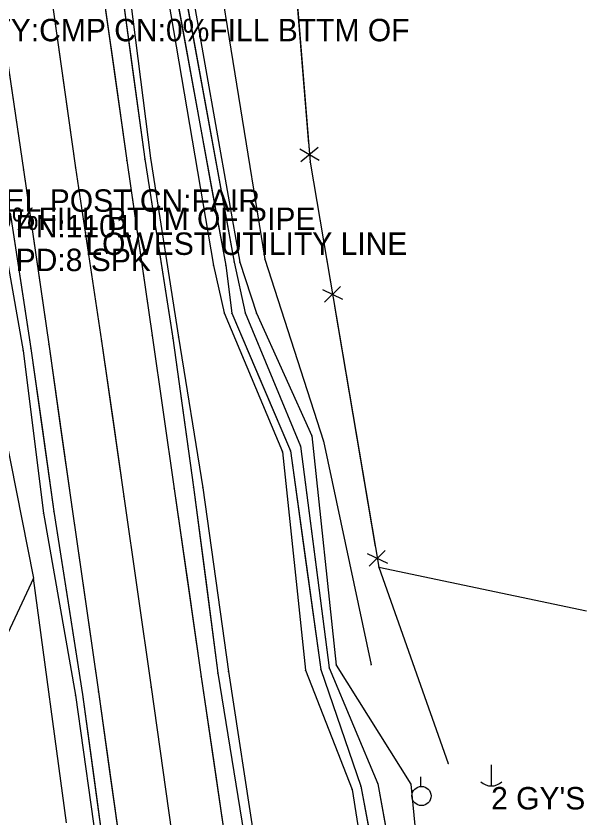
# Model space of a CAD drawing. Extents: x -99999 to 591807, y -99999 to 347168.
# Drawn here: x 588661.3 to 588788.1, y 345244.3 to 345422.9 of the extents above; entities that cross this region are included whole.
import ezdxf

# ---------------------------------------------------------------- set-up
doc = ezdxf.new("R2010")
doc.units = 0
for name, color, linetype in [('S_BREAKLINE', 7, 'Continuous'), ('S_DITCHLINE', 7, 'Continuous'), ('S_EDGE_PAVEMENT', 7, 'Continuous'), ('S_ELECTRIC_UTILITIES_ANNOT', 7, 'Continuous'), ('S_FENCE', 7, 'Continuous'), ('S_FENCE_ANNOT', 7, 'Continuous'), ('S_GRD_PT_SYM', 7, 'Continuous'), ('S_MSC_PT_SYM', 7, 'Continuous'), ('S_PAVEMENT_CROWN', 7, 'Continuous'), ('S_RDW_PT_SYM', 7, 'Continuous'), ('S_SECONDARY_CTL_ANNOT', 7, 'Continuous'), ('S_SHOULDER', 7, 'Continuous'), ('S_SIDE_DRAIN_ANNOT', 7, 'Continuous'), ('S_UTILITY_POLE', 7, 'Continuous'), ('S_UTILITY_POLE_ANNOT', 7, 'Continuous'), ('S_UTL_PT_SYM', 7, 'Continuous')]:
    doc.layers.add(name, color=color, linetype=linetype)

msp = doc.modelspace()

# ---------------------------------------------------------------- linework, layer by layer
at = {"layer": 'S_BREAKLINE'}
for points in [[(588624.24, 345901.93), (588618.85, 345902.22), (588605.5, 345880.61), (588615.62, 345846.94), (588626.77, 345811.58), (588634.39, 345774.77), (588643.3, 345728.51), (588648.82, 345686.6), (588655.41, 345641.18), (588661.15, 345603.84), (588667.75, 345558.22), (588673.72, 345520.6), (588680.03, 345471.84), (588686.17, 345431.09), (588691.15, 345391.28), (588697.45, 345351.38), (588702.87, 345317.84), (588708.54, 345276.89), (588714.45, 345238.55), (588718.86, 345198.93), (588725.64, 345160.39), (588730.67, 345119.29), (588731.09, 345112.27)], [(588617.74, 345892.11), (588627.02, 345863.98), (588634.95, 345829.29), (588643.57, 345794.26), (588660.55, 345743.08), (588666.37, 345681.13), (588673.4, 345633.78), (588679.09, 345577.18), (588687.3, 345524.37), (588688.58, 345508.07), (588680.83, 345498.32), (588692.71, 345440.77), (588705.25, 345367.38), (588707.6, 345356.79), (588720.56, 345325.81), (588725.68, 345277.15), (588736.07, 345250.56), (588745.48, 345190.65)], [(588650.18, 345832.62), (588677.65, 345741.77), (588694.99, 345639.52), (588705.06, 345562.37), (588720.23, 345470.33), (588726.73, 345390.37), (588741.99, 345300.16), (588757.48, 345256.39)], [(588642.9, 345828.16), (588649.84, 345794.79), (588665.62, 345742.31), (588672.08, 345684.23), (588681.44, 345635.79), (588689.72, 345575.35), (588697.32, 345523.2), (588698.7, 345506.43), (588689.37, 345495.16), (588698.11, 345441.67), (588711.09, 345368.1), (588714.76, 345356.74), (588727.1, 345329.38), (588732.56, 345278.32), (588749.18, 345251.82), (588754.96, 345191.81)], [(588698.7, 345506.43), (588704.94, 345441.35), (588716.65, 345368.79), (588729.71, 345328.24), (588740.3, 345278.4)], [(588645.08, 345382.49), (588648.42, 345381.11), (588649.83, 345374.72), (588665.14, 345297.65), (588651.98, 345269.68), (588653.66, 345244.85), (588663.81, 345185.3), (588669.22, 345148.47), (588646.72, 345142.69)], [(588657.87, 345376.65), (588662.84, 345348.37), (588667.37, 345312.15), (588674.5, 345271.59), (588679.6, 345235.06), (588685.37, 345194.37), (588696.43, 345111.07), (588699.23, 345086.02)], [(588672.46, 345243.16), (588665.14, 345297.65)]]:
    msp.add_lwpolyline(points, dxfattribs=at)
at = {"layer": 'S_DITCHLINE'}
for points in [[(588621.84, 345893.69), (588629.96, 345863.53), (588637.77, 345829.01), (588645.75, 345794.64), (588662.97, 345741.75), (588668.58, 345680.85), (588676.01, 345633.28), (588682.43, 345576.4), (588689.45, 345524), (588691.57, 345507.82), (588684.16, 345496.45), (588694.48, 345441.14), (588707.93, 345367.35), (588709.31, 345356.72), (588722.33, 345326.05), (588729.11, 345277.3), (588737.99, 345251.31), (588749.45, 345190.72)], [(588623.83, 345894.43), (588633.9, 345864.11), (588639.2, 345829.29), (588647.45, 345795.03), (588664.28, 345741.74), (588670.78, 345683.92), (588678.95, 345635.24), (588686.91, 345576.28), (588693.9, 345523.47), (588694.27, 345507.04), (588686.96, 345495.31), (588696.5, 345441.16), (588709.78, 345368.13), (588712.25, 345356.79), (588724.62, 345327.12), (588730.93, 345277.7), (588741.81, 345251.89), (588752.43, 345192.99)], [(588694.48, 345441.14), (588697.84, 345422.69), (588701.2, 345404.25), (588704.57, 345385.8), (588707.93, 345367.35), (588709.31, 345356.72), (588715.82, 345341.38), (588722.33, 345326.05), (588725.72, 345301.67), (588729.11, 345277.3), (588733.55, 345264.3), (588737.99, 345251.31), (588740.86, 345236.17), (588743.72, 345221.02), (588746.59, 345205.87), (588749.45, 345190.72)], [(588696.5, 345441.16), (588699.82, 345422.9), (588703.14, 345404.64), (588706.46, 345386.39), (588709.78, 345368.13), (588712.25, 345356.79), (588718.44, 345341.95), (588724.62, 345327.12), (588727.77, 345302.41), (588730.93, 345277.7), (588736.37, 345264.79), (588741.81, 345251.89), (588744.47, 345237.16), (588747.12, 345222.44), (588749.78, 345207.72), (588752.43, 345192.99)]]:
    msp.add_lwpolyline(points, dxfattribs=at)
at = {"layer": 'S_EDGE_PAVEMENT'}
for points in [[(588533.24, 345949.77), (588549.25, 345924.48), (588560.38, 345903.49), (588576.85, 345867.18), (588587.36, 345838.19), (588597.88, 345803.73), (588606.19, 345769.06), (588614.17, 345722.86), (588619.93, 345683.64), (588626.83, 345635.93), (588632.16, 345599.5), (588638.76, 345554.26), (588644.16, 345517.2), (588651.6, 345466.73), (588656.93, 345429.09), (588662.9, 345388.64), (588668.52, 345349.79), (588673.64, 345313.6), (588679.62, 345272.35), (588684.7, 345235.84), (588690.61, 345195.28), (588696.28, 345156.82), (588702.9, 345112.49), (588707.26, 345082.66)], [(588569.44, 345935.94), (588581.55, 345913.63), (588598.25, 345876.18), (588610.02, 345844.44), (588620.66, 345810.06), (588629.03, 345773.8), (588636.94, 345726.71), (588642.85, 345686.06), (588649.62, 345640.56), (588655.14, 345603.07), (588661.71, 345557.63), (588667.45, 345519.25), (588674.48, 345470.93), (588680.21, 345431.06), (588685.9, 345390.75), (588691.57, 345351.74), (588696.47, 345317.62), (588702.47, 345275.72), (588708.04, 345237.72), (588713.42, 345199.12), (588719.22, 345159.84), (588725.04, 345117.97), (588728.1, 345099.84)], [(588680.21, 345431.06), (588683.06, 345410.91), (588685.9, 345390.75), (588688.74, 345371.25), (588691.57, 345351.74), (588694.02, 345334.68), (588696.47, 345317.62), (588699.47, 345296.67), (588702.47, 345275.72), (588705.26, 345256.72), (588708.04, 345237.72), (588710.73, 345218.42), (588713.42, 345199.12), (588716.32, 345179.48), (588719.22, 345159.84), (588722.13, 345138.9), (588725.04, 345117.97), (588728.1, 345099.84)], [(588656.93, 345429.09), (588659.91, 345408.87), (588662.9, 345388.64), (588665.71, 345369.22), (588668.52, 345349.79), (588671.08, 345331.7), (588673.64, 345313.6), (588676.63, 345292.98), (588679.62, 345272.35), (588682.16, 345254.09), (588684.7, 345235.84), (588687.66, 345215.56), (588690.61, 345195.28), (588693.45, 345176.05), (588696.28, 345156.82), (588699.59, 345134.65), (588702.9, 345112.49), (588705.08, 345097.57), (588707.26, 345082.66)]]:
    msp.add_lwpolyline(points, dxfattribs=at)
at = {"layer": 'S_FENCE'}
for p, q in [((588720.23, 345470.33), (588726.73, 345390.37)), ((588724.44, 345393.33), (588728.75, 345390.8)), ((588728.52, 345393.66), (588724.67, 345390.47)), ((588726.73, 345390.37), (588741.99, 345300.16)), ((588729.45, 345362.01), (588733.97, 345359.87)), ((588733.49, 345362.69), (588729.93, 345359.18)), ((588743.45, 345303.84), (588739.89, 345300.33)), ((588739.41, 345303.15), (588743.93, 345301.01)), ((588741.99, 345300.16), (588788.26, 345290.37))]:
    msp.add_line(p, q, dxfattribs=at)
for points in [[(588722.54, 345441.87), (588726.4, 345394.44)], [(588726.73, 345390.37), (588731.26, 345363.61)], [(588732.17, 345358.26), (588741.22, 345304.76)], [(588741.99, 345300.16), (588788.26, 345290.37)]]:
    msp.add_lwpolyline(points, dxfattribs=at)
at = {"layer": 'S_GRD_PT_SYM'}
for points in [[(588691.15, 345391.28), (588691.2, 345391.29), (588691.15, 345391.28), (588691.14, 345391.33), (588691.15, 345391.28), (588691.1, 345391.28), (588691.15, 345391.28), (588691.16, 345391.24)], [(588726.73, 345390.37), (588726.78, 345390.38), (588726.73, 345390.37), (588726.73, 345390.42), (588726.73, 345390.37), (588726.69, 345390.36), (588726.73, 345390.37), (588726.74, 345390.32)], [(588676.68, 345374.71), (588676.68, 345374.76), (588676.68, 345374.71), (588676.63, 345374.71), (588676.68, 345374.71), (588676.68, 345374.66), (588676.68, 345374.71), (588676.73, 345374.71)], [(588709.78, 345368.13), (588709.83, 345368.14), (588709.78, 345368.13), (588709.77, 345368.18), (588709.78, 345368.13), (588709.73, 345368.12), (588709.78, 345368.13), (588709.79, 345368.08)], [(588711.09, 345368.1), (588711.14, 345368.12), (588711.09, 345368.1), (588711.08, 345368.15), (588711.09, 345368.1), (588711.04, 345368.09), (588711.09, 345368.1), (588711.11, 345368.05)], [(588716.65, 345368.79), (588716.7, 345368.8), (588716.65, 345368.79), (588716.64, 345368.84), (588716.65, 345368.79), (588716.6, 345368.77), (588716.65, 345368.79), (588716.67, 345368.74)], [(588705.25, 345367.38), (588705.29, 345367.39), (588705.25, 345367.38), (588705.23, 345367.42), (588705.25, 345367.38), (588705.2, 345367.36), (588705.25, 345367.38), (588705.26, 345367.33)], [(588707.93, 345367.35), (588707.98, 345367.36), (588707.93, 345367.35), (588707.92, 345367.4), (588707.93, 345367.35), (588707.88, 345367.35), (588707.93, 345367.35), (588707.94, 345367.3)], [(588707.6, 345356.79), (588707.64, 345356.81), (588707.6, 345356.79), (588707.58, 345356.84), (588707.6, 345356.79), (588707.55, 345356.77), (588707.6, 345356.79), (588707.62, 345356.75)], [(588709.31, 345356.72), (588709.35, 345356.74), (588709.31, 345356.72), (588709.29, 345356.76), (588709.31, 345356.72), (588709.26, 345356.7), (588709.31, 345356.72), (588709.33, 345356.67)], [(588712.25, 345356.79), (588712.3, 345356.81), (588712.25, 345356.79), (588712.24, 345356.83), (588712.25, 345356.79), (588712.21, 345356.77), (588712.25, 345356.79), (588712.27, 345356.74)], [(588714.76, 345356.74), (588714.81, 345356.76), (588714.76, 345356.74), (588714.74, 345356.79), (588714.76, 345356.74), (588714.72, 345356.72), (588714.76, 345356.74), (588714.78, 345356.69)], [(588697.45, 345351.38), (588697.5, 345351.39), (588697.45, 345351.38), (588697.44, 345351.43), (588697.45, 345351.38), (588697.4, 345351.38), (588697.45, 345351.38), (588697.46, 345351.33)], [(588662.84, 345348.37), (588662.89, 345348.38), (588662.84, 345348.37), (588662.83, 345348.42), (588662.84, 345348.37), (588662.79, 345348.36), (588662.84, 345348.37), (588662.84, 345348.32)], [(588727.1, 345329.38), (588727.15, 345329.39), (588727.1, 345329.38), (588727.1, 345329.43), (588727.1, 345329.38), (588727.06, 345329.38), (588727.1, 345329.38), (588727.11, 345329.33)], [(588724.62, 345327.12), (588724.67, 345327.12), (588724.62, 345327.12), (588724.61, 345327.17), (588724.62, 345327.12), (588724.57, 345327.11), (588724.62, 345327.12), (588724.62, 345327.07)], [(588729.71, 345328.24), (588729.75, 345328.25), (588729.71, 345328.24), (588729.69, 345328.29), (588729.71, 345328.24), (588729.66, 345328.23), (588729.71, 345328.24), (588729.72, 345328.19)], [(588720.56, 345325.81), (588720.61, 345325.81), (588720.56, 345325.81), (588720.56, 345325.86), (588720.56, 345325.81), (588720.51, 345325.8), (588720.56, 345325.81), (588720.57, 345325.76)], [(588722.33, 345326.05), (588722.38, 345326.05), (588722.33, 345326.05), (588722.32, 345326.1), (588722.33, 345326.05), (588722.28, 345326.04), (588722.33, 345326.05), (588722.34, 345326)], [(588702.87, 345317.84), (588702.92, 345317.85), (588702.87, 345317.84), (588702.86, 345317.89), (588702.87, 345317.84), (588702.82, 345317.83), (588702.87, 345317.84), (588702.88, 345317.79)], [(588667.37, 345312.15), (588667.42, 345312.16), (588667.37, 345312.15), (588667.36, 345312.2), (588667.37, 345312.15), (588667.32, 345312.15), (588667.37, 345312.15), (588667.38, 345312.11)], [(588741.99, 345300.16), (588742.04, 345300.18), (588741.99, 345300.16), (588741.98, 345300.21), (588741.99, 345300.16), (588741.95, 345300.15), (588741.99, 345300.16), (588742.01, 345300.12)], [(588665.14, 345297.65), (588665.09, 345297.64), (588665.14, 345297.65), (588665.14, 345297.6), (588665.14, 345297.65), (588665.19, 345297.65), (588665.14, 345297.65), (588665.13, 345297.7)], [(588665.14, 345297.65), (588665.18, 345297.63), (588665.14, 345297.65), (588665.16, 345297.69), (588665.14, 345297.65), (588665.09, 345297.67), (588665.14, 345297.65), (588665.11, 345297.6)], [(588725.68, 345277.15), (588725.73, 345277.16), (588725.68, 345277.15), (588725.67, 345277.19), (588725.68, 345277.15), (588725.64, 345277.13), (588725.68, 345277.15), (588725.7, 345277.1)], [(588729.11, 345277.3), (588729.16, 345277.31), (588729.11, 345277.3), (588729.09, 345277.34), (588729.11, 345277.3), (588729.06, 345277.28), (588729.11, 345277.3), (588729.13, 345277.25)], [(588730.93, 345277.7), (588730.98, 345277.72), (588730.93, 345277.7), (588730.91, 345277.74), (588730.93, 345277.7), (588730.89, 345277.68), (588730.93, 345277.7), (588730.95, 345277.65)], [(588732.56, 345278.32), (588732.6, 345278.35), (588732.56, 345278.32), (588732.53, 345278.36), (588732.56, 345278.32), (588732.51, 345278.29), (588732.56, 345278.32), (588732.58, 345278.28)], [(588740.3, 345278.4), (588740.35, 345278.41), (588740.3, 345278.4), (588740.29, 345278.45), (588740.3, 345278.4), (588740.25, 345278.39), (588740.3, 345278.4), (588740.31, 345278.35)], [(588708.54, 345276.89), (588708.59, 345276.9), (588708.54, 345276.89), (588708.53, 345276.94), (588708.54, 345276.89), (588708.49, 345276.88), (588708.54, 345276.89), (588708.55, 345276.84)], [(588674.5, 345271.59), (588674.55, 345271.59), (588674.5, 345271.59), (588674.49, 345271.64), (588674.5, 345271.59), (588674.45, 345271.58), (588674.5, 345271.59), (588674.51, 345271.54)], [(588757.48, 345256.39), (588757.53, 345256.41), (588757.48, 345256.39), (588757.46, 345256.44), (588757.48, 345256.39), (588757.43, 345256.38), (588757.48, 345256.39), (588757.5, 345256.35)], [(588736.07, 345250.56), (588736.12, 345250.57), (588736.07, 345250.56), (588736.06, 345250.61), (588736.07, 345250.56), (588736.02, 345250.55), (588736.07, 345250.56), (588736.07, 345250.51)], [(588737.99, 345251.31), (588738.04, 345251.32), (588737.99, 345251.31), (588737.98, 345251.36), (588737.99, 345251.31), (588737.94, 345251.3), (588737.99, 345251.31), (588738, 345251.26)], [(588741.81, 345251.89), (588741.86, 345251.9), (588741.81, 345251.89), (588741.8, 345251.94), (588741.81, 345251.89), (588741.76, 345251.88), (588741.81, 345251.89), (588741.82, 345251.84)], [(588749.18, 345251.82), (588749.23, 345251.83), (588749.18, 345251.82), (588749.18, 345251.87), (588749.18, 345251.82), (588749.13, 345251.82), (588749.18, 345251.82), (588749.19, 345251.77)]]:
    msp.add_lwpolyline(points, close=True, dxfattribs=at)
at = {"layer": 'S_MSC_PT_SYM'}
for points in [[(588726.73, 345390.37), (588726.73, 345390.42), (588726.73, 345390.37), (588726.68, 345390.37), (588726.73, 345390.37), (588726.73, 345390.32), (588726.73, 345390.37), (588726.78, 345390.37)], [(588741.99, 345300.16), (588741.99, 345300.21), (588741.99, 345300.16), (588741.94, 345300.16), (588741.99, 345300.16), (588741.99, 345300.11), (588741.99, 345300.16), (588742.04, 345300.16)]]:
    msp.add_lwpolyline(points, dxfattribs=at)
at = {"layer": 'S_PAVEMENT_CROWN'}
for points in [[(588560.06, 345929.96), (588571.31, 345908.67), (588587.66, 345872.48), (588598.75, 345842.4), (588609.73, 345806.6), (588617.97, 345771.15), (588625.58, 345724.38), (588631.45, 345685.22), (588638.38, 345638.52), (588643.85, 345601.75), (588650.48, 345555.87), (588655.89, 345518.36), (588662.96, 345470.1), (588668.73, 345430.24), (588674.46, 345389.14), (588680.31, 345350.53), (588685.24, 345315.85), (588691.31, 345273.41), (588696.56, 345236.41), (588702.29, 345197.14), (588707.93, 345158.2), (588714.7, 345114.95), (588717.67, 345091.03)], [(588668.73, 345430.24), (588671.59, 345409.69), (588674.46, 345389.14), (588677.38, 345369.83), (588680.31, 345350.53), (588682.77, 345333.19), (588685.24, 345315.85), (588688.27, 345294.63), (588691.31, 345273.41), (588693.93, 345254.91), (588696.56, 345236.41), (588699.42, 345216.78), (588702.29, 345197.14), (588705.11, 345177.67), (588707.93, 345158.2), (588711.32, 345136.58), (588714.7, 345114.95), (588717.67, 345091.03)]]:
    msp.add_lwpolyline(points, dxfattribs=at)
at = {"layer": 'S_RDW_PT_SYM'}
for points in [[(588685.9, 345390.75), (588685.95, 345390.76), (588685.9, 345390.75), (588685.9, 345390.8), (588685.9, 345390.75), (588685.85, 345390.75), (588685.9, 345390.75), (588685.91, 345390.7)], [(588689.91, 345391.05), (588689.95, 345391.06), (588689.91, 345391.05), (588689.9, 345391.1), (588689.91, 345391.05), (588689.86, 345391.04), (588689.91, 345391.05), (588689.91, 345391)], [(588662.9, 345388.64), (588662.95, 345388.65), (588662.9, 345388.64), (588662.89, 345388.69), (588662.9, 345388.64), (588662.85, 345388.64), (588662.9, 345388.64), (588662.91, 345388.59)], [(588674.46, 345389.14), (588674.51, 345389.15), (588674.46, 345389.14), (588674.45, 345389.19), (588674.46, 345389.14), (588674.41, 345389.13), (588674.46, 345389.14), (588674.46, 345389.09)], [(588680.31, 345350.53), (588680.36, 345350.54), (588680.31, 345350.53), (588680.3, 345350.58), (588680.31, 345350.53), (588680.26, 345350.52), (588680.31, 345350.53), (588680.32, 345350.48)], [(588691.57, 345351.74), (588691.62, 345351.74), (588691.57, 345351.74), (588691.57, 345351.79), (588691.57, 345351.74), (588691.52, 345351.73), (588691.57, 345351.74), (588691.58, 345351.69)], [(588696.15, 345351.16), (588696.2, 345351.17), (588696.15, 345351.16), (588696.14, 345351.21), (588696.15, 345351.16), (588696.1, 345351.16), (588696.15, 345351.16), (588696.16, 345351.11)], [(588664.56, 345348.83), (588664.61, 345348.84), (588664.56, 345348.83), (588664.55, 345348.88), (588664.56, 345348.83), (588664.51, 345348.83), (588664.56, 345348.83), (588664.57, 345348.79)], [(588668.52, 345349.79), (588668.57, 345349.79), (588668.52, 345349.79), (588668.52, 345349.84), (588668.52, 345349.79), (588668.48, 345349.78), (588668.52, 345349.79), (588668.53, 345349.74)], [(588696.47, 345317.62), (588696.52, 345317.62), (588696.47, 345317.62), (588696.46, 345317.67), (588696.47, 345317.62), (588696.42, 345317.61), (588696.47, 345317.62), (588696.47, 345317.57)], [(588700.78, 345317.94), (588700.82, 345317.95), (588700.78, 345317.94), (588700.77, 345317.99), (588700.78, 345317.94), (588700.73, 345317.93), (588700.78, 345317.94), (588700.78, 345317.89)], [(588685.24, 345315.85), (588685.29, 345315.86), (588685.24, 345315.85), (588685.23, 345315.9), (588685.24, 345315.85), (588685.19, 345315.84), (588685.24, 345315.85), (588685.24, 345315.8)], [(588673.64, 345313.6), (588673.69, 345313.61), (588673.64, 345313.6), (588673.63, 345313.65), (588673.64, 345313.6), (588673.59, 345313.6), (588673.64, 345313.6), (588673.65, 345313.55)], [(588669.67, 345312.57), (588669.72, 345312.58), (588669.67, 345312.57), (588669.66, 345312.62), (588669.67, 345312.57), (588669.62, 345312.56), (588669.67, 345312.57), (588669.68, 345312.52)], [(588702.47, 345275.72), (588702.52, 345275.73), (588702.47, 345275.72), (588702.47, 345275.77), (588702.47, 345275.72), (588702.42, 345275.71), (588702.47, 345275.72), (588702.48, 345275.67)], [(588706.2, 345276.52), (588706.25, 345276.53), (588706.2, 345276.52), (588706.19, 345276.57), (588706.2, 345276.52), (588706.15, 345276.52), (588706.2, 345276.52), (588706.21, 345276.48)], [(588691.31, 345273.41), (588691.36, 345273.41), (588691.31, 345273.41), (588691.3, 345273.46), (588691.31, 345273.41), (588691.26, 345273.4), (588691.31, 345273.41), (588691.32, 345273.36)], [(588676.08, 345271.74), (588676.13, 345271.75), (588676.08, 345271.74), (588676.07, 345271.79), (588676.08, 345271.74), (588676.03, 345271.73), (588676.08, 345271.74), (588676.09, 345271.69)], [(588679.62, 345272.35), (588679.67, 345272.36), (588679.62, 345272.35), (588679.61, 345272.4), (588679.62, 345272.35), (588679.57, 345272.34), (588679.62, 345272.35), (588679.62, 345272.3)]]:
    msp.add_lwpolyline(points, close=True, dxfattribs=at)
at = {"layer": 'S_SHOULDER'}
for points in [[(588684.51, 345430.85), (588689.91, 345391.05), (588696.15, 345351.16), (588700.78, 345317.94), (588706.2, 345276.52), (588712.42, 345238.08), (588717.59, 345199.4), (588723.46, 345160.01), (588729.09, 345119.02), (588730.26, 345112.01), (588733.24, 345109.71), (588731.27, 345105.97), (588728.55, 345100.82)], [(588684.51, 345430.85), (588687.21, 345410.95), (588689.91, 345391.05), (588693.03, 345371.11), (588696.15, 345351.16), (588698.46, 345334.55), (588700.78, 345317.94), (588703.49, 345297.23), (588706.2, 345276.52), (588709.31, 345257.3), (588712.42, 345238.08), (588715, 345218.74), (588717.59, 345199.4), (588720.53, 345179.7), (588723.46, 345160.01), (588726.28, 345139.51), (588729.09, 345119.02), (588730.26, 345112.01), (588733.24, 345109.71), (588731.27, 345105.97), (588728.55, 345100.82)], [(588659.97, 345379.12), (588664.56, 345348.83), (588669.67, 345312.57), (588676.08, 345271.74), (588681.01, 345235.14), (588686.53, 345194.68), (588691.96, 345156.28), (588697.69, 345111.33), (588702.07, 345083.39), (588705.48, 345081.62)], [(588659.97, 345379.12), (588662.27, 345363.98), (588664.56, 345348.83), (588667.12, 345330.7), (588669.67, 345312.57), (588672.88, 345292.16), (588676.08, 345271.74), (588678.55, 345253.44), (588681.01, 345235.14), (588683.77, 345214.91), (588686.53, 345194.68), (588689.24, 345175.48), (588691.96, 345156.28), (588694.83, 345133.81), (588697.69, 345111.33), (588699.88, 345097.36), (588702.07, 345083.39), (588705.48, 345081.62)]]:
    msp.add_lwpolyline(points, dxfattribs=at)
at = {"layer": 'S_UTILITY_POLE'}
for p, q in [((588767, 345256.09), (588767, 345251.36)), ((588751.4, 345251.29), (588751.4, 345253.4))]:
    msp.add_line(p, q, dxfattribs=at)
msp.add_circle((588751.52, 345249.15), 2.13, dxfattribs=at)
msp.add_arc((588767.06, 345254.79), 3.41, 226.3972, 313.6028, dxfattribs=at)
at = {"layer": 'S_UTL_PT_SYM'}
msp.add_lwpolyline([(588676.68, 345374.71), (588676.68, 345374.76), (588676.68, 345374.71), (588676.63, 345374.71), (588676.68, 345374.71), (588676.68, 345374.66), (588676.68, 345374.71), (588676.73, 345374.71)], dxfattribs=at)

# ---------------------------------------------------------------- texts
at = {"layer": 'S_ELECTRIC_UTILITIES_ANNOT'}
msp.add_text('LOWEST UTILITY LINE', height=5, dxfattribs=at).set_placement((588676.68, 345369.71))
at = {"layer": 'S_FENCE_ANNOT'}
msp.add_text('5 BARB STEEL POST CN:FAIR', height=5, dxfattribs=at).set_placement((588620.07, 345379.32))
at = {"layer": 'S_SECONDARY_CTL_ANNOT'}
for s, p in [('PN:1101', (588661.17, 345373.6)), ('PD:8 SPK', (588661.17, 345366.1))]:
    msp.add_text(s, height=5, dxfattribs=at).set_placement(p)
at = {"layer": 'S_SIDE_DRAIN_ANNOT'}
for s, p in [('DI:24 TY:CMP CN:0%FILL BTTM OF ', (588638.15, 345417.31)), ('CN:0%FILL BTTM OF PIPE', (588645.07, 345375.27))]:
    msp.add_text(s, height=5, dxfattribs=at).set_placement(p)
at = {"layer": 'S_UTILITY_POLE_ANNOT'}
msp.add_text("2 GY'S", height=5, dxfattribs=at).set_placement((588767.02, 345246.15))

doc.saveas('drawing.dxf')
